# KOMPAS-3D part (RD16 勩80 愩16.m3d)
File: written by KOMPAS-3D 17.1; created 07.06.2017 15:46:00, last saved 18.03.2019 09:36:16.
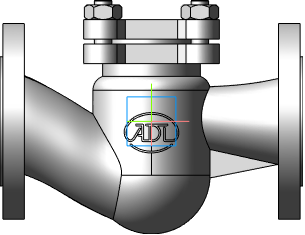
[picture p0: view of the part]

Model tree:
1. Операция без истории:2  (labels: Сталь 20  ГОСТ 1050-88)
